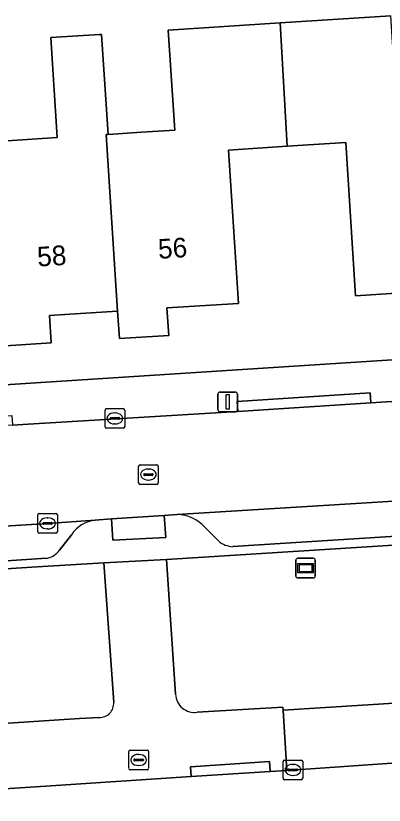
# Model space of a CAD drawing. Extents: x 159626 to 160723, y 388173 to 389416.
# Drawn here: x 160389.46 to 160408.21, y 388326.47 to 388366.65 of the extents above; entities that cross this region are included whole.
import ezdxf

# ---------------------------------------------------------------- set-up
doc = ezdxf.new("R2010")
doc.units = 0
for name, color, linetype in [('IMGEO_Erf', 7, 'Continuous'), ('IMGEO_Groenvoorziening', 7, 'Continuous'), ('IMGEO_Kolk', 7, 'Continuous'), ('IMGEO_Lichtmast', 7, 'Continuous'), ('IMGEO_Pand', 7, 'Continuous'), ('IMGEO_Pand_nummerreeks', 7, 'Continuous'), ('IMGEO_Parkeervlak_open', 7, 'Continuous'), ('IMGEO_Rijbaan_lokaal_open', 7, 'Continuous'), ('IMGEO_Rijbaan_regionaal_gesloten', 7, 'Continuous'), ('IMGEO_Rioolput', 7, 'Continuous'), ('IMGEO_Verklikker', 7, 'Continuous'), ('IMGEO_Voetpad_open', 7, 'Continuous')]:
    doc.layers.add(name, color=color, linetype=linetype)

msp = doc.modelspace()

# ---------------------------------------------------------------- linework, layer by layer
at = {"layer": 'IMGEO_Erf'}
for points in [[(160397.219, 388365.917), (160402.918, 388366.284), (160408.549, 388366.646)], [(160384.92, 388360.019), (160391.564, 388360.446), (160391.236, 388365.534), (160393.723, 388365.693), (160393.828, 388365.7), (160394.156, 388360.612), (160395.852, 388360.721), (160397.548, 388360.83), (160397.219, 388365.917)], [(160410.388, 388352.627), (160406.76, 388352.394), (160406.256, 388360.198), (160403.27, 388360.006), (160400.286, 388359.815), (160400.79, 388352.01), (160397.152, 388351.775), (160397.242, 388350.38), (160394.729, 388350.218), (160394.638, 388351.615), (160392.208, 388351.459), (160391.174, 388351.392), (160391.263, 388349.996), (160388.672, 388349.828)], [(160349.131, 388345.29), (160389.96, 388347.928), (160437.814, 388351.02)]]:
    msp.add_lwpolyline(points, dxfattribs=at)
at = {"layer": 'IMGEO_Groenvoorziening'}
for points in [[(160398.695, 388331.202), (160403.057, 388331.467), (160403.067, 388331.305), (160441.302, 388333.713), (160442.552, 388335.356), (160467.15, 388336.963), (160467.275, 388335.225), (160501.835, 388337.484), (160501.213, 388347.873), (160500, 388347.802), (160491.895, 388347.305), (160490.539, 388345.566), (160490.061, 388345.143)], [(160489.377, 388344.926), (160452.877, 388342.587), (160451.214, 388344.256), (160439.719, 388343.519), (160437.971, 388341.554), (160397.13, 388338.982), (160397.594, 388332.119)], [(160394.441, 388331.706), (160393.947, 388338.809), (160390.545, 388338.593), (160278.645, 388331.479)], [(160501.982, 388335.024), (160501.835, 388337.484), (160467.275, 388335.225), (160441.302, 388333.713), (160403.067, 388331.305), (160403.258, 388328.243), (160416.129, 388329.131), (160431.58, 388330.029), (160482.533, 388333.323), (160501.552, 388334.526)], [(160355.899, 388329.309), (160371.306, 388331.042), (160378.988, 388329.988), (160392.7, 388330.877), (160393.698, 388330.938)]]:
    msp.add_lwpolyline(points, dxfattribs=at)
for centre, radius, start, end in [((160398.547, 388332.144), 0.953, 181.4732, 278.9464), ((160393.733, 388331.647), 0.71, 267.1408, 4.755)]:
    msp.add_arc(centre, radius, start, end, dxfattribs=at)
at = {"layer": 'IMGEO_Kolk'}
for p, q in [((160394.001, 388345.728), (160394.001, 388346.58)), ((160394.076, 388346.654), (160394.928, 388346.654)), ((160394.489, 388346.434), (160394.514, 388346.434)), ((160395.002, 388346.58), (160395.002, 388345.728)), ((160394.26, 388346.148), (160394.26, 388346.16)), ((160394.698, 388346.111), (160394.3, 388346.111)), ((160394.303, 388346.197), (160394.701, 388346.197)), ((160394.744, 388346.16), (160394.744, 388346.148)), ((160394.928, 388345.654), (160394.076, 388345.654)), ((160394.512, 388345.874), (160394.487, 388345.874)), ((160390.573, 388340.388), (160390.573, 388341.24)), ((160390.648, 388341.314), (160391.5, 388341.314)), ((160391.574, 388341.24), (160391.574, 388340.388)), ((160390.832, 388340.808), (160390.832, 388340.82)), ((160391.27, 388340.771), (160390.872, 388340.771)), ((160390.875, 388340.857), (160391.273, 388340.857)), ((160391.061, 388341.094), (160391.086, 388341.094)), ((160391.316, 388340.82), (160391.316, 388340.808)), ((160391.5, 388340.314), (160390.648, 388340.314)), ((160391.084, 388340.534), (160391.059, 388340.534)), ((160403.063, 388327.84), (160403.063, 388328.692)), ((160403.138, 388328.766), (160403.99, 388328.766)), ((160404.064, 388328.692), (160404.064, 388327.84)), ((160403.322, 388328.26), (160403.322, 388328.272)), ((160403.365, 388328.309), (160403.763, 388328.309)), ((160403.551, 388328.546), (160403.576, 388328.546)), ((160403.806, 388328.272), (160403.806, 388328.26)), ((160403.76, 388328.223), (160403.362, 388328.223)), ((160403.574, 388327.986), (160403.549, 388327.986)), ((160403.99, 388327.766), (160403.138, 388327.766))]:
    msp.add_line(p, q, dxfattribs=at)
for points in [[(160394.001, 388345.728), (160394.001, 388346.58)], [(160394.076, 388346.654), (160394.928, 388346.654)], [(160395.002, 388346.58), (160395.002, 388345.728)], [(160394.928, 388345.654), (160394.076, 388345.654)], [(160390.573, 388340.388), (160390.573, 388341.24)], [(160390.648, 388341.314), (160391.5, 388341.314)], [(160391.574, 388341.24), (160391.574, 388340.388)], [(160391.5, 388340.314), (160390.648, 388340.314)], [(160403.063, 388327.84), (160403.063, 388328.692)], [(160403.138, 388328.766), (160403.99, 388328.766)], [(160404.064, 388328.692), (160404.064, 388327.84)], [(160403.99, 388327.766), (160403.138, 388327.766)]]:
    msp.add_lwpolyline(points, dxfattribs=at)
for centre, radius, start, end in [((160394.078, 388346.578), 0.0765, 91.552, 178.448), ((160394.078, 388346.578), 0.0765, 91.552, 178.448), ((160394.926, 388346.578), 0.0765, 1.552, 88.448), ((160394.926, 388346.578), 0.0765, 1.552, 88.448), ((160394.3, 388346.157), 0.0403, 85.8775, 175.7526), ((160394.297, 388346.147), 0.0366, 178.938, 274.7102), ((160394.701, 388346.154), 0.043, 264.8664, 352.4533), ((160394.705, 388346.159), 0.0386, 1.7309, 96.639), ((160394.078, 388345.73), 0.0765, 181.552, 268.448), ((160394.078, 388345.73), 0.0765, 181.552, 268.448), ((160394.926, 388345.73), 0.0765, 271.552, 358.448), ((160394.926, 388345.73), 0.0765, 271.552, 358.448), ((160390.65, 388341.238), 0.0765, 91.552, 178.448), ((160390.65, 388341.238), 0.0765, 91.552, 178.448), ((160391.498, 388341.238), 0.0765, 1.552, 88.448), ((160391.498, 388341.238), 0.0765, 1.552, 88.448), ((160390.872, 388340.817), 0.0403, 85.8775, 175.7526), ((160390.869, 388340.807), 0.0366, 178.938, 274.7102), ((160391.273, 388340.814), 0.043, 264.8664, 352.4533), ((160391.277, 388340.819), 0.0386, 1.7309, 96.639), ((160390.65, 388340.39), 0.0765, 181.552, 268.448), ((160390.65, 388340.39), 0.0765, 181.552, 268.448), ((160391.498, 388340.39), 0.0765, 271.552, 358.448), ((160391.498, 388340.39), 0.0765, 271.552, 358.448), ((160403.14, 388328.69), 0.0765, 91.552, 178.448), ((160403.14, 388328.69), 0.0765, 91.552, 178.448), ((160403.988, 388328.69), 0.0765, 1.552, 88.448), ((160403.988, 388328.69), 0.0765, 1.552, 88.448), ((160403.362, 388328.269), 0.0403, 85.8775, 175.7526), ((160403.359, 388328.259), 0.0366, 178.938, 274.7102), ((160403.763, 388328.266), 0.043, 264.8664, 352.4533), ((160403.767, 388328.271), 0.0386, 1.7309, 96.639), ((160403.14, 388327.842), 0.0765, 181.552, 268.448), ((160403.14, 388327.842), 0.0765, 181.552, 268.448), ((160403.988, 388327.842), 0.0765, 271.552, 358.448), ((160403.988, 388327.842), 0.0765, 271.552, 358.448)]:
    msp.add_arc(centre, radius, start, end, dxfattribs=at)
for centre, major_axis, ratio, start_param, end_param in [((160394.488, 388346.154), (-0.387, 0.002), 0.722429, 4.712389, 7.853982), ((160394.513, 388346.154), (-0.39, 0.002), 0.717154, 1.570796, 4.712389), ((160391.06, 388340.814), (-0.387, 0.002), 0.722429, 4.712389, 7.853982), ((160391.085, 388340.814), (-0.39, 0.002), 0.717154, 1.570796, 4.712389), ((160403.55, 388328.266), (-0.387, 0.002), 0.722429, 4.712389, 7.853982), ((160403.575, 388328.266), (-0.39, 0.002), 0.717154, 1.570796, 4.712389)]:
    msp.add_ellipse(centre, major_axis=major_axis, ratio=ratio, start_param=start_param, end_param=end_param, dxfattribs=at)
at = {"layer": 'IMGEO_Lichtmast'}
for p, q in [((160399.749, 388346.594), (160399.749, 388347.394)), ((160399.749, 388347.394), (160399.749, 388346.594)), ((160399.849, 388347.494), (160400.639, 388347.494)), ((160400.639, 388347.494), (160399.849, 388347.494)), ((160400.739, 388347.394), (160400.739, 388346.594)), ((160400.739, 388346.594), (160400.739, 388347.394)), ((160400.639, 388346.494), (160399.849, 388346.494)), ((160399.849, 388346.494), (160400.639, 388346.494))]:
    msp.add_line(p, q, dxfattribs=at)
msp.add_lwpolyline([(160400.169, 388347.369), (160400.319, 388347.369), (160400.319, 388346.619), (160400.169, 388346.619), (160400.169, 388347.369)], dxfattribs=at)
for centre, start, end in [((160399.849, 388347.394), 90, 180), ((160399.849, 388347.394), 90, 180), ((160400.639, 388347.394), 0, 90), ((160400.639, 388347.394), 360, 90), ((160399.849, 388346.594), 180, 270), ((160399.849, 388346.594), 180, 270), ((160400.639, 388346.594), 270, 0), ((160400.639, 388346.594), 270, 0)]:
    msp.add_arc(centre, 0.1, start, end, dxfattribs=at)
at = {"layer": 'IMGEO_Pand'}
for points in [[(160403.27, 388360.006), (160406.256, 388360.198), (160406.76, 388352.394), (160410.388, 388352.627), (160410.477, 388351.23), (160413.068, 388351.399), (160412.977, 388352.798), (160412.269, 388361.777), (160408.877, 388361.559), (160408.549, 388366.646), (160402.918, 388366.284)], [(160400.286, 388359.815), (160403.27, 388360.006), (160402.918, 388366.284), (160397.219, 388365.917), (160397.548, 388360.83), (160395.852, 388360.721), (160394.156, 388360.612), (160394.054, 388360.605), (160394.638, 388351.615), (160394.729, 388350.218), (160397.242, 388350.38), (160397.152, 388351.775), (160400.79, 388352.01)], [(160394.054, 388360.605), (160394.156, 388360.612), (160393.828, 388365.7), (160393.723, 388365.693), (160391.236, 388365.534), (160391.564, 388360.446), (160384.92, 388360.019), (160385.326, 388353.639), (160388.317, 388353.831), (160388.484, 388351.219), (160388.672, 388349.828), (160391.263, 388349.996), (160391.174, 388351.392), (160392.208, 388351.459), (160394.638, 388351.615)]]:
    msp.add_lwpolyline(points, close=True, dxfattribs=at)
at = {"layer": 'IMGEO_Parkeervlak_open'}
for points in [[(160439.893, 388343.883), (160432.068, 388343.36), (160412.561, 388342.181), (160397.667, 388341.259)], [(160400.5, 388339.628), (160437.492, 388341.985)], [(160393.502, 388340.981), (160391.07, 388340.815), (160373.652, 388339.721), (160354.162, 388338.48), (160333.018, 388337.172), (160313.523, 388335.939), (160295.034, 388334.739), (160277.03, 388333.628), (160275.549, 388333.506)], [(160399.092, 388340.61), (160399.786, 388339.9)], [(160391.688, 388339.454), (160392.291, 388340.228)], [(160278.438, 388331.908), (160309.462, 388333.599), (160390.519, 388339), (160391.029, 388339.034)]]:
    msp.add_lwpolyline(points, dxfattribs=at)
for centre, radius, start, end in [((160397.63, 388339.289), 1.97, 42.1028, 88.9245), ((160393.683, 388339.34), 1.651, 96.2851, 147.4616), ((160400.592, 388340.941), 1.317, 232.2766, 266.0145), ((160390.813, 388340.099), 1.087, 281.4389, 323.5822)]:
    msp.add_arc(centre, radius, start, end, dxfattribs=at)
at = {"layer": 'IMGEO_Rijbaan_lokaal_open'}
msp.add_lwpolyline([(160333.018, 388337.172), (160354.162, 388338.48), (160373.652, 388339.721), (160391.07, 388340.815), (160393.502, 388340.981), (160394.33, 388341.044), (160397.011, 388341.212), (160397.667, 388341.259), (160412.561, 388342.181), (160432.068, 388343.36), (160439.893, 388343.883), (160439.541, 388349.019), (160425.779, 388348.13), (160418.998, 388347.671), (160407.535, 388346.951), (160400.759, 388346.511), (160390.09, 388345.858), (160389.293, 388345.809), (160382.517, 388345.349), (160370.956, 388344.596), (160364.171, 388344.172), (160352.061, 388343.382)], dxfattribs=at)
at = {"layer": 'IMGEO_Rijbaan_regionaal_gesloten'}
msp.add_lwpolyline([(160498.569, 388330.843), (160501.711, 388331.041), (160501.552, 388334.526), (160482.533, 388333.323), (160431.58, 388330.029), (160416.129, 388329.131), (160403.258, 388328.243), (160402.405, 388328.188), (160398.382, 388327.927), (160391.245, 388327.456), (160384.175, 388326.99), (160373.808, 388325.977), (160353.994, 388323.671), (160342.589, 388322.211), (160341.716, 388322.099)], dxfattribs=at)
at = {"layer": 'IMGEO_Rioolput'}
for p, q in [((160395.71, 388342.872), (160395.71, 388343.724)), ((160395.785, 388343.798), (160396.637, 388343.798)), ((160396.198, 388343.578), (160396.223, 388343.578)), ((160396.711, 388343.724), (160396.711, 388342.872)), ((160395.969, 388343.292), (160395.969, 388343.304)), ((160396.407, 388343.255), (160396.009, 388343.255)), ((160396.012, 388343.341), (160396.41, 388343.341)), ((160396.453, 388343.304), (160396.453, 388343.292)), ((160396.637, 388342.798), (160395.785, 388342.798)), ((160396.221, 388343.018), (160396.196, 388343.018)), ((160395.211, 388328.346), (160395.211, 388329.198)), ((160395.286, 388329.272), (160396.138, 388329.272)), ((160396.212, 388329.198), (160396.212, 388328.346)), ((160395.47, 388328.766), (160395.47, 388328.778)), ((160395.908, 388328.729), (160395.51, 388328.729)), ((160395.513, 388328.815), (160395.911, 388328.815)), ((160395.699, 388329.052), (160395.724, 388329.052)), ((160395.954, 388328.778), (160395.954, 388328.766)), ((160396.138, 388328.272), (160395.286, 388328.272)), ((160395.722, 388328.492), (160395.697, 388328.492))]:
    msp.add_line(p, q, dxfattribs=at)
for points in [[(160395.71, 388342.872), (160395.71, 388343.724)], [(160395.785, 388343.798), (160396.637, 388343.798)], [(160396.711, 388343.724), (160396.711, 388342.872)], [(160396.637, 388342.798), (160395.785, 388342.798)], [(160395.211, 388328.346), (160395.211, 388329.198)], [(160395.286, 388329.272), (160396.138, 388329.272)], [(160396.212, 388329.198), (160396.212, 388328.346)], [(160396.138, 388328.272), (160395.286, 388328.272)]]:
    msp.add_lwpolyline(points, dxfattribs=at)
for centre, radius, start, end in [((160395.787, 388343.722), 0.0765, 91.552, 178.448), ((160395.787, 388343.722), 0.0765, 91.552, 178.448), ((160396.635, 388343.722), 0.0765, 1.552, 88.448), ((160396.635, 388343.722), 0.0765, 1.552, 88.448), ((160396.009, 388343.301), 0.0403, 85.8775, 175.7526), ((160396.006, 388343.291), 0.0366, 178.938, 274.7102), ((160396.41, 388343.298), 0.043, 264.8664, 352.4533), ((160396.414, 388343.303), 0.0386, 1.7309, 96.639), ((160395.787, 388342.874), 0.0765, 181.552, 268.448), ((160395.787, 388342.874), 0.0765, 181.552, 268.448), ((160396.635, 388342.874), 0.0765, 271.552, 358.448), ((160396.635, 388342.874), 0.0765, 271.552, 358.448), ((160395.288, 388329.196), 0.0765, 91.552, 178.448), ((160395.288, 388329.196), 0.0765, 91.552, 178.448), ((160396.136, 388329.196), 0.0765, 1.552, 88.448), ((160396.136, 388329.196), 0.0765, 1.552, 88.448), ((160395.51, 388328.775), 0.0403, 85.8775, 175.7526), ((160395.507, 388328.765), 0.0366, 178.938, 274.7102), ((160395.911, 388328.772), 0.043, 264.8664, 352.4533), ((160395.915, 388328.777), 0.0386, 1.7309, 96.639), ((160395.288, 388328.348), 0.0765, 181.552, 268.448), ((160395.288, 388328.348), 0.0765, 181.552, 268.448), ((160396.136, 388328.348), 0.0765, 271.552, 358.448), ((160396.136, 388328.348), 0.0765, 271.552, 358.448)]:
    msp.add_arc(centre, radius, start, end, dxfattribs=at)
for centre, major_axis, ratio, start_param, end_param in [((160396.197, 388343.298), (-0.387, 0.002), 0.722429, 4.712389, 7.853982), ((160396.222, 388343.298), (-0.39, 0.002), 0.717154, 1.570796, 4.712389), ((160395.698, 388328.772), (-0.387, 0.002), 0.722429, 4.712389, 7.853982), ((160395.723, 388328.772), (-0.39, 0.002), 0.717154, 1.570796, 4.712389)]:
    msp.add_ellipse(centre, major_axis=major_axis, ratio=ratio, start_param=start_param, end_param=end_param, dxfattribs=at)
at = {"layer": 'IMGEO_Verklikker'}
for p, q in [((160403.715, 388338.134), (160403.715, 388338.934)), ((160403.715, 388338.934), (160403.715, 388338.134)), ((160403.815, 388339.034), (160404.605, 388339.034)), ((160404.605, 388339.034), (160403.815, 388339.034)), ((160404.705, 388338.934), (160404.705, 388338.134)), ((160404.705, 388338.134), (160404.705, 388338.934)), ((160404.605, 388338.034), (160403.815, 388338.034)), ((160403.815, 388338.034), (160404.605, 388338.034))]:
    msp.add_line(p, q, dxfattribs=at)
for points in [[(160403.816, 388338.766), (160404.604, 388338.766), (160404.604, 388338.302), (160403.816, 388338.302), (160403.816, 388338.766)], [(160403.881, 388338.701), (160403.881, 388338.367), (160404.539, 388338.367), (160404.539, 388338.701), (160403.881, 388338.701)]]:
    msp.add_lwpolyline(points, dxfattribs=at)
for centre, start, end in [((160403.815, 388338.934), 90, 180), ((160403.815, 388338.934), 90, 180), ((160404.605, 388338.934), 0, 90), ((160404.605, 388338.934), 360, 90), ((160403.815, 388338.134), 180, 270), ((160403.815, 388338.134), 180, 270), ((160404.605, 388338.134), 270, 0), ((160404.605, 388338.134), 270, 0)]:
    msp.add_arc(centre, 0.1, start, end, dxfattribs=at)
at = {"layer": 'IMGEO_Voetpad_open'}
for points in [[(160442.014, 388350.988), (160441.998, 388351.273), (160437.814, 388351.02), (160389.96, 388347.928), (160349.131, 388345.29), (160347.594, 388345.191), (160272.851, 388340.361), (160268.041, 388339.984)], [(160352.061, 388343.382), (160364.171, 388344.172), (160364.14, 388344.671), (160370.925, 388345.095), (160370.956, 388344.596), (160382.517, 388345.349), (160382.484, 388345.847), (160389.26, 388346.307), (160389.293, 388345.809), (160390.09, 388345.858), (160400.759, 388346.511), (160400.727, 388347.009), (160407.503, 388347.449), (160407.535, 388346.951), (160418.998, 388347.671), (160418.965, 388348.169), (160425.746, 388348.628), (160425.779, 388348.13), (160439.541, 388349.019), (160442.162, 388349.188), (160442.014, 388350.988)], [(160278.645, 388331.479), (160390.545, 388338.593), (160393.947, 388338.809), (160397.13, 388338.982), (160437.971, 388341.554), (160439.719, 388343.519), (160451.214, 388344.256), (160452.877, 388342.587), (160489.377, 388344.926)], [(160437.492, 388341.985), (160400.5, 388339.628)], [(160397.667, 388341.259), (160397.011, 388341.212), (160397.099, 388340.097), (160394.401, 388339.95), (160394.33, 388341.044), (160393.502, 388340.981)], [(160399.786, 388339.9), (160399.092, 388340.61)], [(160392.291, 388340.228), (160391.688, 388339.454)], [(160391.029, 388339.034), (160390.519, 388339), (160309.462, 388333.599), (160278.438, 388331.908)], [(160397.594, 388332.119), (160397.13, 388338.982), (160393.947, 388338.809), (160394.441, 388331.706)], [(160384.175, 388326.99), (160391.245, 388327.456), (160398.382, 388327.927), (160398.351, 388328.428), (160402.374, 388328.686), (160402.405, 388328.188), (160403.258, 388328.243), (160403.067, 388331.305)], [(160403.067, 388331.305), (160403.057, 388331.467), (160398.695, 388331.202)], [(160393.698, 388330.938), (160392.7, 388330.877), (160378.988, 388329.988), (160371.306, 388331.042), (160355.899, 388329.309), (160355.559, 388329.272), (160355.756, 388327.455), (160355.817, 388326.885)]]:
    msp.add_lwpolyline(points, dxfattribs=at)
for points in [[(160400.759, 388346.511), (160407.535, 388346.951), (160407.503, 388347.449), (160400.727, 388347.009)], [(160397.011, 388341.212), (160394.33, 388341.044), (160394.401, 388339.95), (160397.099, 388340.097)], [(160402.374, 388328.686), (160398.351, 388328.428), (160398.382, 388327.927), (160402.405, 388328.188)]]:
    msp.add_lwpolyline(points, close=True, dxfattribs=at)
for centre, radius, start, end in [((160397.63, 388339.289), 1.97, 42.1028, 88.9245), ((160393.683, 388339.34), 1.651, 96.2851, 147.4616), ((160400.592, 388340.941), 1.317, 232.2766, 266.0145), ((160390.813, 388340.099), 1.087, 281.4389, 323.5822), ((160398.547, 388332.144), 0.953, 181.4732, 278.9464), ((160393.733, 388331.647), 0.71, 267.1408, 4.755)]:
    msp.add_arc(centre, radius, start, end, dxfattribs=at)

# ---------------------------------------------------------------- texts
at = {"layer": 'IMGEO_Pand_nummerreeks'}
for s, p in [('56', (160396.727, 388354.274)), ('58', (160390.577, 388353.879))]:
    msp.add_text(s, height=1, rotation=3.6784, dxfattribs=at).set_placement(p)

doc.saveas('drawing.dxf')
